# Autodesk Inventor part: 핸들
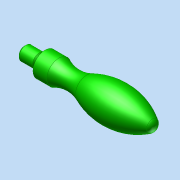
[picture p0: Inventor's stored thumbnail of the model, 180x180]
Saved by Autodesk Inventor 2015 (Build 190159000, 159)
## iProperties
Created: 2026-09
Part Number: 핸들
Material: 일반
Document SubType Name: Modeling
Designer: SCD-A06
Density: 1 g/cm^3
Appearance: 기본값
Author: SCD-A06
Author: jhkim
Creation Date: 2026-08-27
Sending System: Autodesk Inventor 2027
Preprocessor: ST-DEVELOPER v20.1
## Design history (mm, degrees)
node "핸들1"
node "솔리드1"
node "기준1"
